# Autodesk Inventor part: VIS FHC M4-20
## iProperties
Created: 2004-11
Part Number: VIS FHC M4-20
Document SubType Name: Modeling
Designer: Bruno
Manufacturer: Standard
Standards Organization: Custom
Author: Bruno
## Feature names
1. Base1
